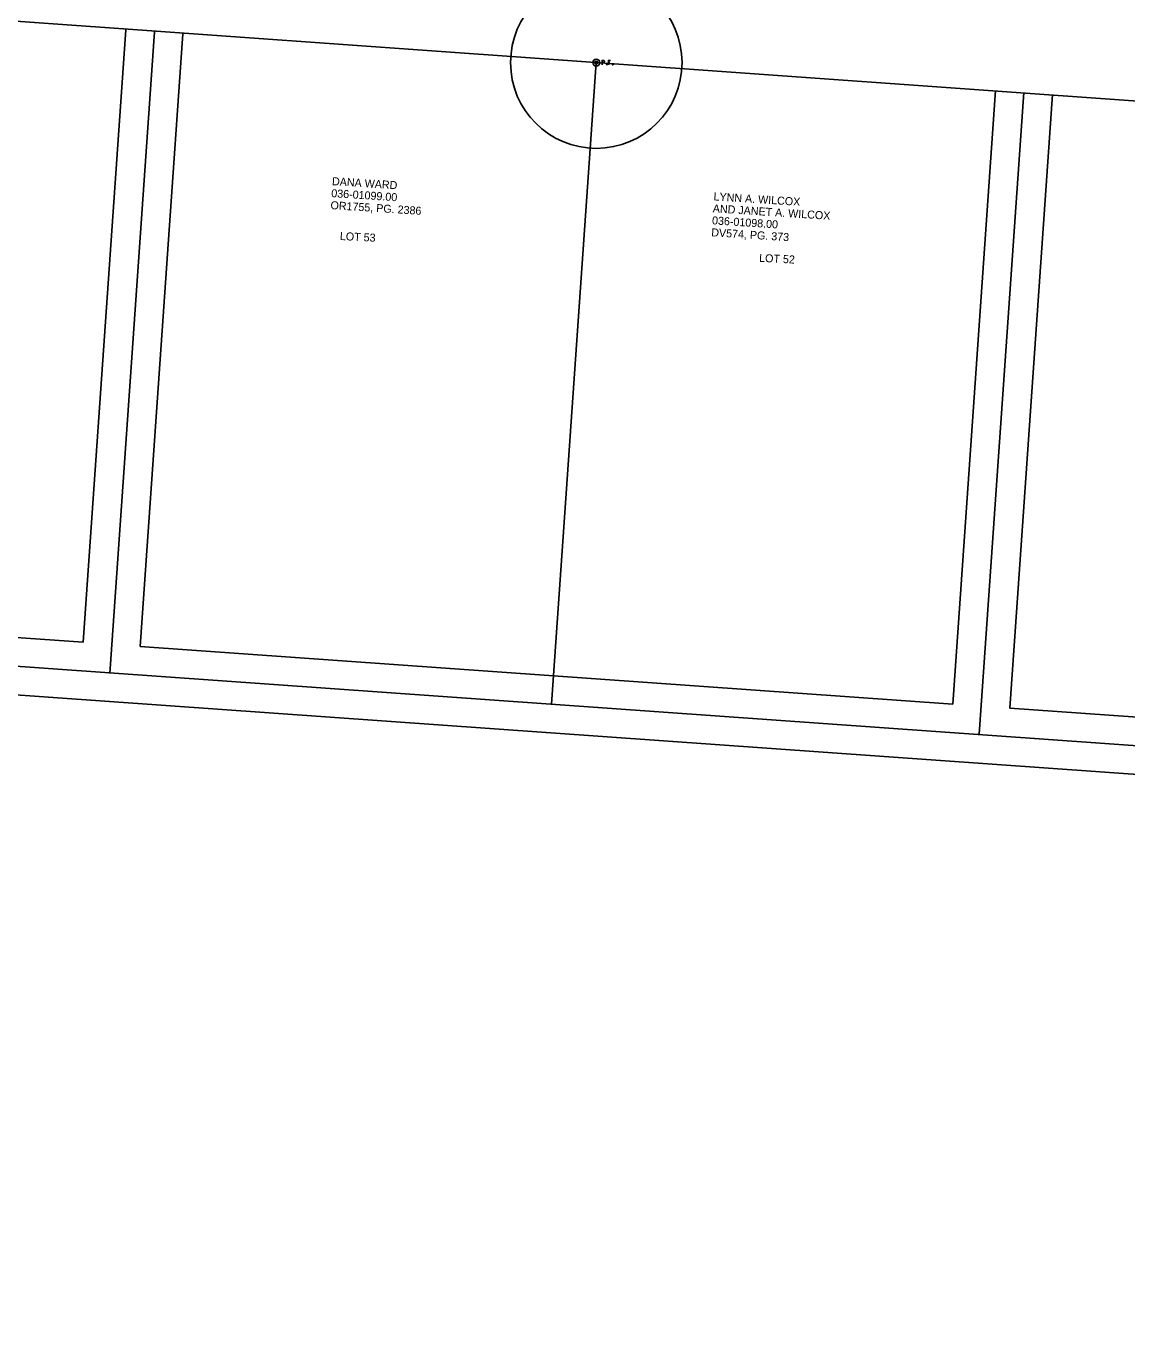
# Model space of a CAD drawing. Extents: x 1898254 to 1901377, y 701554 to 704886.
# Drawn here: x 1898968.1 to 1899353.1, y 702797.1 to 703258.5 of the extents above; entities that cross this region are included whole.
import ezdxf

# ---------------------------------------------------------------- set-up
doc = ezdxf.new("R2010")
doc.units = 0
for name, color, linetype in [('DV_X_Property_Line', 7, 'Continuous'), ('DV_X_Text', 7, 'Continuous'), ('RW_X_Esmt_General', 7, 'Continuous'), ('RW_X_Fee_RW', 7, 'Continuous'), ('SC_Scratch1', 7, 'Continuous'), ('SC_Scratch2', 7, 'Continuous'), ('SV_X_Mon_Cells_Found', 7, 'Continuous')]:
    doc.layers.add(name, color=color, linetype=linetype)

msp = doc.modelspace()

# ---------------------------------------------------------------- linework, layer by layer
at = {"layer": 'DV_X_Property_Line'}
for p, q in [((1898997.3, 703032.17), (1899012.93, 703256.63)), ((1899151.93, 703021.4), (1899167.56, 703245.86)), ((1899301.56, 703010.98), (1899317.2, 703235.44)), ((1899469, 702998.85), (1898413.79, 703073.89))]:
    msp.add_line(p, q, dxfattribs=at)
at = {"layer": 'RW_X_Esmt_General'}
for p, q in [((1898988.04, 703043.08), (1899002.96, 703257.32)), ((1899007.99, 703041.66), (1899022.91, 703255.93)), ((1899292.27, 703021.45), (1899307.22, 703236.13)), ((1899312.22, 703020.03), (1899327.17, 703234.74)), ((1899458.32, 702989.59), (1898413.09, 703063.91)), ((1898988.04, 703043.08), (1898713.73, 703062.59)), ((1899292.27, 703021.45), (1899007.99, 703041.66)), ((1899459.74, 703009.54), (1899312.22, 703020.03))]:
    msp.add_line(p, q, dxfattribs=at)
at = {"layer": 'RW_X_Fee_RW'}
msp.add_line((1899763.77, 703203.46), (1898449.4, 703296.93), dxfattribs=at)
at = {"layer": 'SC_Scratch1'}
msp.add_circle((1899167.56, 703245.86), 30, dxfattribs=at)
at = {"layer": 'SC_Scratch2'}
msp.add_circle((1899815.76, 703229.84), 1561.35, dxfattribs=at)
at = {"layer": 'SV_X_Mon_Cells_Found'}
for points in [[(1899169.56, 703245.06), (1899169.56, 703246.66), (1899170.09, 703246.66), (1899170.14, 703246.64), (1899170.22, 703246.62), (1899170.25, 703246.59), (1899170.28, 703246.57), (1899170.33, 703246.51), (1899170.36, 703246.44), (1899170.38, 703246.34), (1899170.38, 703246.19), (1899170.37, 703246.14), (1899170.35, 703246.07), (1899170.31, 703245.98), (1899170.26, 703245.94), (1899170.23, 703245.91), (1899170.17, 703245.89), (1899170.09, 703245.88), (1899169.56, 703245.88)], [(1899171.2, 703245.27), (1899171.25, 703245.27), (1899171.29, 703245.25), (1899171.32, 703245.2), (1899171.32, 703245.13), (1899171.29, 703245.08), (1899171.25, 703245.06), (1899171.2, 703245.06), (1899171.17, 703245.08), (1899171.13, 703245.13), (1899171.13, 703245.2), (1899171.17, 703245.25), (1899171.2, 703245.27)], [(1899172.57, 703246.66), (1899171.8, 703246.66), (1899171.8, 703245.06)], [(1899171.8, 703245.88), (1899172.34, 703245.88)], [(1899173.35, 703245.27), (1899173.4, 703245.27), (1899173.44, 703245.25), (1899173.47, 703245.2), (1899173.47, 703245.13), (1899173.44, 703245.08), (1899173.4, 703245.06), (1899173.35, 703245.06), (1899173.31, 703245.08), (1899173.28, 703245.13), (1899173.28, 703245.2), (1899173.31, 703245.25), (1899173.35, 703245.27)]]:
    msp.add_lwpolyline(points, dxfattribs=at)
for radius in [1.2, 0.495]:
    msp.add_circle((1899167.56, 703245.86), radius, dxfattribs=at)

# ---------------------------------------------------------------- texts
at = {"layer": 'DV_X_Text'}
for s, rotation, p in [('DANA WARD', 356.3351, (1899075.02, 703203.02)), ('036-01099.00', 356.3351, (1899074.76, 703198.83)), ('OR1755, PG. 2386', 356.3351, (1899074.49, 703194.64)), ('LYNN A. WILCOX', 356.3351, (1899208.52, 703197.7)), ('036-01098.00', 356.3351, (1899207.98, 703189.32)), ('AND JANET A. WILCOX', 356.3351, (1899208.25, 703193.51)), ('DV574, PG. 373', 356.3351, (1899207.72, 703185.13)), ('LOT 53', 357.0949, (1899077.78, 703183.83)), ('LOT 52', 357.0949, (1899224.48, 703176.19))]:
    msp.add_text(s, height=2.8, rotation=rotation, dxfattribs=at).set_placement(p)

doc.saveas('drawing.dxf')
